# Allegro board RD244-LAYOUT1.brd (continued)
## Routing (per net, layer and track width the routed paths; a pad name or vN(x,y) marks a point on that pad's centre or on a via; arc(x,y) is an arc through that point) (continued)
OUTA1: length 257.6
  CONDUCTIVE3 w0.3: A101.1 106.5,135.28 106.5,110.46 109.99,106.97 117.53,106.97 118.9,105.6 118.9,101.94 122.61,98.23 122.61,93.02 118.23,88.64 118.23,24.02 119.09,23.16 139.66,23.16 142.75,20.07 142.75,10.23 149.22,3.76 189.49,3.76 194.79,9.06 209.76,9.06 210.2,9.5 221,9.5 v1(221.35,9.15)
  BOTTOM w0.3: v1(221.35,9.15) 223.05,7.45 225.4,7.45 226.16,8.21 227.57,8.21
  BOTTOM w0.55: IC303.14 227.57,8.21
OUTA2: length 7.7
  BOTTOM w0.3: R354.1 243.26,6.35 243.59,6.67 244.37,6.67 ; 246.48,6.65 v1(247.25,6.65) ; 238.41,8.21 238.84,8.21 240.7,6.35 241.59,6.35
  BOTTOM w0.45: R354.2 241.59,6.35 ; R356.2 244.37,6.67 ; R355.2 246.48,6.65
  BOTTOM w0.55: 238.41,8.21 IC303.3
OUTB1: length 268.5
  CONDUCTIVE3 w0.3: A101.2 113.04,141.51 112.45,142.1 108.8,142.1 105.2,138.5 105.2,109.9 109.21,105.89 116.81,105.89 118.03,104.67 118.03,101.6 121.65,97.98 121.65,93.25 117.55,89.15 117.55,23.18 118.5,22.23 139.25,22.23 141.4,20.08 141.4,9.72 148.42,2.7 190.46,2.7 195.76,8 217.93,8 218.03,8.1 v1(221.35,8.1)
  BOTTOM w0.3: v1(221.35,8.1) 222.99,6.46 225.69,6.46 226.16,6.93 227.46,6.93
  BOTTOM w0.55: 227.46,6.93 IC303.13
OUTB2: length 12
  BOTTOM w0.3: 238.53,6.93 238.97,6.93 240.75,5.15 241.61,5.15 ; 246.6,5.55 v1(251.6,5.55) ; R357.1 243.13,5.15 243.51,5.53 244.37,5.53
  BOTTOM w0.45: R357.2 241.61,5.15 ; R359.2 244.37,5.53 ; R358.2 246.6,5.55
  BOTTOM w0.55: 238.53,6.93 IC303.4
OUTC1: length 228.8
  CONDUCTIVE4 w0.3: A102.1 110.5,109.06 112.2,107.36 113.43,107.36 118.84,101.95 118.84,96.44 116.7,94.3 116.7,25.61 119.34,22.97 140.58,22.97 145.04,18.51 145.04,12.65 155.4,2.29 201.56,2.29 206.17,6.9 v1(221.35,6.9)
  BOTTOM w0.3: v1(221.35,6.9) 222.59,5.67 227.46,5.67
  BOTTOM w0.55: 227.46,5.67 IC303.12
OUTC2: length 24.7
  TOP w0.3: DP254.1 v1(247.9,2.9)
  BOTTOM w0.3: 258.88,7.97 255.55,7.97 250.47,2.9 v1(247.9,2.9) 246.6,2.9 ; R360.2 240.76,3.95 239.05,5.67 238.54,5.67 ; 244.37,2.88 243.68,2.88 R360.1
  BOTTOM w0.4: 258.88,7.97 IC251.20
  BOTTOM w0.45: R362.2 244.37,2.88 ; R361.2 246.6,2.9
  BOTTOM w0.55: 238.54,5.67 IC303.5
OUTD1: length 243.8
  CONDUCTIVE4 w0.3: A102.2 113.04,125.4 111.94,126.5 109.5,126.5 107.8,124.8 107.8,109.3 111.07,106.03 113.57,106.03 118.18,101.42 118.18,97.03 115.94,94.79 115.94,24.83 118.63,22.14 139.21,22.14 144.11,17.24 144.11,11.49 153.95,1.65 202.37,1.65 206.52,5.8 v1(221.35,5.8)
  BOTTOM w0.3: v1(221.35,5.8) 222.75,4.39 227.46,4.39
  BOTTOM w0.55: 227.46,4.39 IC303.11
OUTD2: length 14.3
  BOTTOM w0.3: v1(251.9,2.85) 256.38,7.33 258.88,7.33 ; 238.34,4.39 239.21,4.39 240.8,2.8 241.57,2.8
  BOTTOM w0.4: 258.88,7.33 IC251.19
  BOTTOM w0.45: R363.2 241.57,2.8
  BOTTOM w0.55: 238.34,4.39 IC303.6
OUTE: length 47.7
  CONDUCTIVE4 w0.5: v1(261.2,7.3) 261.2,11.7 v1(255.5,17.4) 255.5,18.72 256.06,19.28 256.06,45.65 252.6,49.11
  BOTTOM w0.3: 260.23,6.67 260.57,6.67 v1(261.2,7.3)
  BOTTOM w0.4: IC251.18 260.23,6.67
  vias: v1(259.39,117.8) v1(261.36,69.34)
OUTF: length 68.8
  CONDUCTIVE3 w0.5: v1(261.2,6) 262.3,7.1 262.3,13.18 v1(261.05,14.43) 257.25,18.23 257.25,44.56 253.39,48.42
  CONDUCTIVE4 w0.5: v1(259.87,120.42) 259.23,119.78 257.29,119.78 254.43,122.64 244.59,122.64 243.73,123.5 v1(239.42,123.5)
  vias: v1(238.83,77.39) v1(261.35,72.02)
PFC_OFF: length 12.7
  TOP w0.3: 116.32,3.58 114.67,3.58 ; 116.5,4.6 116.5,10.2 DP51.1 118.7,12.4 v1(120.5,12.4)
  TOP w0.4: 114.67,3.58 114.5,3.58
  TOP w0.45: R308.2 116.32,3.58 ; R308.1 116.5,4.6
PN: length 452.1
  TOP w0.3: 219.28,6.22 219.28,5.43
  TOP w0.45: 219.28,6.4 219.28,6.22 ; 219.28,5.43 219.28,5.25
  TOP w0.5: T401.4 223.85,19.5 C414.1
  TOP w0.7: v1(119.59,94.34) v1(119.59,93.54)
  CONDUCTIVE3 w0.3: v1(132.3,4.3) 133.43,5.43 133.43,6.11 134.93,7.61 134.93,14.88 130.11,19.7 116.9,19.7 112.1,24.5 112.1,59.7 113.83,61.43 113.83,93.39 113.54,93.68 A51.4 112.41,97.07 112.41,92.71 113.13,91.99 113.13,62.01 111.34,60.22 111.34,24.08 116.32,19.1 129.72,19.1 134.19,14.63 134.19,7.72 133.64,7.17 v1(133.13,7.17)
  CONDUCTIVE4 w0.5: C54.1 92.24,5.15 96.73,9.64 96.73,15.08 RY1.1
  CONDUCTIVE4 w1: A51.4 113.54,95.39 114.6,94.33 v1(114.6,13.4)
  BOTTOM w0.3: T401.4 222.43,22.5 C407.1 ; 118.17,13.18 118.17,13.92 ; v1(133.13,7.17) 131.36,7.17
  BOTTOM w0.36: 131.36,7.17 131.1,7.17
  BOTTOM w0.45: 118.17,13.92 R60.1 ; R63.1 118.17,13.18
  BOTTOM w0.5: 188.8,31.8 184.3,27.3 178.82,27.3
  BOTTOM w1: A102.4 A101.4
  BOTTOM w1.405: 178.82,27.3 R102.1
  vias: v1(91.8,16.7) v1(108.7,1.9) v1(113.4,13.4) v1(117.6,6.6) v1(118.2,15) v1(123.8,11.3) v1(124.6,11.3) v1(125.83,5.12) v1(126.62,5.12) v1(127.31,15.21) v1(131,14.7) v1(131.1,8.2) v1(199.5,7) v1(199.5,6.2) v1(199.5,3.2) v1(208.5,10.3) v1(209.3,17.43) v1(209.3,16.73) v1(211.3,10.2) v1(212.1,10.2) v1(215.83,2.81) v1(218.32,10.3) v1(218.39,1.64) v1(225.7,9.5) v1(226.79,2.31)
SIG1: length 73.9
  CONDUCTIVE3 w0.5: C2.2 9.48,70.02 FH2.2 FH2.1
  BOTTOM w5: L1.3 44.75,94.25 C1.1 ; 3.17,50.05 3.17,40.33 TB1.2
SIG0013: length 142
  TOP w2: R3.2 R4.1
  CONDUCTIVE3 w0.3: v1(97,3.8) 88.8,12 88.8,26.6 81.9,33.5 C9.1
  CONDUCTIVE3 w0.5: L2.1 53.38,19.88 53.38,14.38 46.44,7.44 25.56,7.44 C7.2
  CONDUCTIVE4 w0.5: L2.4 40.4,27.5 34.47,21.57 34.47,18.97 C8.2
  BOTTOM w2: R3.2 R4.1
  vias: v1(77.9,49.5) v1(77.9,48.7) v1(77.9,47.9) v1(77.9,47.1) v1(77.9,46.3) v1(77.9,45.5) v1(77.9,44.7) v1(78.7,49.5) v1(78.7,48.7) v1(78.7,47.9) v1(78.7,47.1) v1(78.7,46.3) v1(78.7,45.5) v1(78.7,44.7) v1(79.5,49.5) v1(79.5,48.7) v1(79.5,47.9) v1(79.5,47.1) v1(79.5,46.3) v1(79.5,45.5) v1(79.5,44.7) v1(80.3,49.5) v1(80.3,48.7) v1(80.3,47.9) v1(80.3,47.1) v1(80.3,46.3) v1(80.3,45.5) v1(80.3,44.7) v1(81.1,49.5) v1(81.1,48.7) v1(81.1,47.9) v1(81.1,47.1) v1(81.1,46.3) v1(81.1,45.5) v1(81.1,44.7) v1(81.9,49.5) v1(81.9,48.7) v1(81.9,47.9) v1(81.9,47.1) v1(81.9,46.3) v1(81.9,45.5) v1(81.9,44.7)
SIG0032: length 14.4
  BOTTOM w0.3: 124.17,4.72 124.17,3.88 ; 125.2,3.7 128,3.7 128.38,4.08 128.38,4.67 ; 124.17,5.08 124.17,8.72 123.53,9.38 123,9.38 ; 128.28,6.01 128.28,6.93 128.32,6.98 128.32,7.77 ; 128.28,5.07 128.28,5.79
  BOTTOM w0.4: 123,9.38 IC51.13
  BOTTOM w0.45: 124.17,5.08 C63.2 124.17,4.72 ; R65.1 125.2,3.7 ; 124.17,3.88 R65.2 ; 128.38,4.67 R66.2 ; 128.28,4.9 128.28,5.07 ; 128.28,5.79 128.28,6.01
  BOTTOM w0.6: 128.32,7.77 128.32,7.97
SIG0033: length 0.9
  BOTTOM w0.3: 119.86,14.1 119.14,14.1
  BOTTOM w0.45: R59.1 119.86,14.1 ; 119.14,14.1 R60.2
SIG43: length 4.8
  BOTTOM w0.3: R67.2 119.53,5.17 120.1,5.17 ; 120.4,6.03 121.67,6.03 122.47,6.83 122.47,7.77
  BOTTOM w0.45: 120.1,5.17 C65.1 ; C65.2 120.4,6.03
  BOTTOM w0.6: 122.47,7.77 IC51.11
SIG45: length 2.2
  BOTTOM w0.3: C66.2 119.55,8.2 119.72,8.03 120.1,8.03 ; C67.1 119.83,7.17 119.75,7.1 119.39,7.1
  BOTTOM w0.45: 120.1,8.03 C67.2 ; 119.39,7.1 R68.2
SIG47:
  vias: v1(126.8,12.6)
SIG51: length 1.4
  BOTTOM w0.3: 128.32,14.23 128.32,14.75 C58.2
  BOTTOM w0.6: 128.32,14.23 128.32,14.03
SIG52: length 3.6
  BOTTOM w0.3: 121.78,13.28 119.9,13.28 119.62,13 R63.2
  BOTTOM w0.4: 121.78,13.28 IC51.19
SIG0052: length 11.6
  CONDUCTIVE3 w0.5: v1(246.1,129.7) v1(251.9,129.7) v1(257.7,129.7)
SIG53: length 4.6
  BOTTOM w0.3: 126.5,6.95 126.5,9.2 127.33,10.03 127.77,10.03
  BOTTOM w0.4: 127.77,10.03 128.32,10.03
  BOTTOM w0.45: 126.5,6.78 126.5,6.95
SIG0053: length 12
  CONDUCTIVE3 w0.5: v1(276.01,129.7) v1(270.26,129.7) 264.7,129.7 v1(264.2,130.2)
SIG54: length 5.9
  BOTTOM w0.3: 127.63,10.68 126.97,10.68 125.4,9.1 125.4,7
  BOTTOM w0.4: 128.32,10.68 127.63,10.68
  BOTTOM w0.45: 125.4,7 125.4,6.83
SIG0054: length 15
  CONDUCTIVE3 w0.5: v1(264.15,82.5) v1(269.92,82.5) v1(275.68,82.5)
  BOTTOM w0.5: 264.7,76.9 264.7,78.44 ; 266.8,77.14 266.8,78.44
  BOTTOM w0.8: D205.A 266.8,77.14
  BOTTOM w0.83: 266.8,78.44 R206.1 ; 264.7,78.44 R205.1
  BOTTOM w1.1: D204.C 264.7,76.9
SIG0055: length 12.6
  CONDUCTIVE3 w0.5: v1(257.89,82.5) v1(252.11,82.5) 251.22,83.39 v1(245.64,83.39)
SIG56: length 3.3
  BOTTOM w0.3: 129.9,15.05 129.9,13.6 129.57,13.28 128.86,13.28
  BOTTOM w0.4: 128.32,13.28 128.86,13.28
  BOTTOM w0.45: 129.9,15.05 R58.2
SIG116: length 2.2
  BOTTOM w0.5: 246.39,76.4 244.86,76.4
  BOTTOM w0.8: 244.86,76.4 D201.A
  BOTTOM w1.1: 246.75,76.4 246.39,76.4
SIG121: length 13.4
  CONDUCTIVE4 w0.5: v1(260.41,73.25) 264.43,73.25 267.06,70.62 v1(270.4,70.62)
  BOTTOM w0.5: 258.03,73.2 257.01,73.2
  BOTTOM w0.92: C202.2 258.03,73.2 ; 257.01,73.2 C201.2
SIG124: length 11.4
  CONDUCTIVE4 w0.5: v1(258.54,121.21) 259.06,121.73 262.29,121.73 265.09,118.93 v1(268.56,118.93)
SIG136: length 26.8
  TOP w0.5: IC501.5 265,42.86 265.51,43.37 267.93,43.37 269,42.3 269,40.86
  TOP w0.83: 269,40.86 R504.1
  CONDUCTIVE3 w0.5: v1(277.7,40.6) 279.3,42.2 v1(284.8,42.2) 290.5,42.2 ; v1(296.4,42.2) v1(290.6,42.2)
SIG148: length 4.3
  TOP w0.3: v1(266.96,7.44) 268.42,8.9 270.5,8.9
  TOP w0.45: R252.2 270.5,8.9
SIG149: length 3.3
  TOP w0.3: v1(267.8,6.7) 268.9,7.8 270.5,7.8
  TOP w0.45: R253.2 270.5,7.8
SIG150: length 5.8
  TOP w0.3: v1(268.7,6.1) 269.3,6.7 270.62,6.7
  TOP w0.45: R254.2 270.62,6.7
  BOTTOM w0.3: 266.12,6.03 267.18,6.03 267.45,5.75 268.35,5.75 v1(268.7,6.1)
  BOTTOM w0.4: IC251.8 266.12,6.03
SIG151: length 5.6
  TOP w0.3: 270.55,5.6 v1(269.7,5.6)
  TOP w0.45: R255.2 270.55,5.6
  BOTTOM w0.3: 266.12,5.38 266.77,5.38 267.05,5.1 269.2,5.1 v1(269.7,5.6)
  BOTTOM w0.4: IC251.9 266.12,5.38
SIG181: length 4.5
  BOTTOM w0.3: 264.7,2.2 264.1,2.2 263.5,2.8 263.5,3.6 263.98,4.08 264.6,4.08
  BOTTOM w0.4: IC251.11 264.6,4.08
  BOTTOM w0.45: 264.7,2.2 R257.2
SIG199: length 85
  CONDUCTIVE3 w0.5: L2.2 49.25,40.75 37.15,40.75 C4.2
  CONDUCTIVE4 w0.5: C5.2 21.5,46.85 27.15,52.5 L2.3
SIG00792: length 1.1
  TOP w0.3: 106.88,3.02 107.62,3.02
  TOP w0.45: 107.62,3.02 C304.2 ; C305.2 106.88,3.02
SIG00795: length 1.1
  TOP w0.3: 216.58,4.38 217.32,4.38
  TOP w0.45: 217.32,4.38 C307.2 ; C308.2 216.58,4.38
SIG00797: length 4.8
  TOP w0.3: 220.75,1.45 223.32,1.45 223.85,1.98 ; IC302.4 220.72,2.12 220.57,1.98 220.57,1.61
  TOP w0.45: 220.75,1.45 R315.2 220.57,1.61
SIG007110: length 6.6
  TOP w0.3: 110.52,5.08 114.33,5.08 ; 110.35,5.52 110.35,6.27 109.92,6.7 109.92,7.38
  TOP w0.4: 110.52,5.08 110.35,5.08 110.35,5.52 ; 114.33,5.08 114.5,5.08
SIG007129: length 2.1
  TOP w0.3: 217.5,2.58 217.07,2.58 DP305.1
SIG008104: length 1.1
  BOTTOM w0.3: 201.43,8.98 201.43,8.24
  BOTTOM w0.45: 201.43,8.24 R413.2 ; C410.2 201.43,8.98
SIG008110:
  vias: v1(251.64,40.07) v1(251.64,39.37) v1(251.62,31.63) v1(251.62,30.93) v1(252.34,40.07) v1(252.34,39.37) v1(252.32,31.63) v1(252.32,30.93) v1(253.04,40.07) v1(253.04,39.37) v1(253.02,31.63) v1(253.02,30.93) v1(253.74,40.07) v1(253.74,39.37) v1(253.72,31.63) v1(253.72,30.93) v1(254.44,40.07) v1(254.44,39.37) v1(254.42,31.63) v1(254.42,30.93) v1(255.14,40.07) v1(255.14,39.37) v1(255.12,31.63) v1(255.12,30.93)
SIG008111: length 74.9
  BOTTOM w0.3: 205.63,14.9 192.85,14.9 189.55,11.6 C401.2
  BOTTOM w0.65: 205.63,14.9 IC401.7
  BOTTOM w1: F401.2 186.44,11.6 C401.2 187.7,18.15 203.65,34.1 212.42,34.1 213.42,35.1 T401.1
SIG008112: length 11.6
  BOTTOM w1: T401.3 218.7,27.5 Q401.D
SIG008113: length 5.8
  TOP w0.3: v1(206.15,10.15) 206.15,11.02 208.7,13.57
  BOTTOM w0.3: v1(202.85,10.71) 203.24,11.1 203.8,11.1
  BOTTOM w0.45: 203.8,11.1 R409.2
  vias: v1(204.5,12.4)
SIG008116: length 15.1
  BOTTOM w0.3: T401.5 219.31,18.7 218.69,18.08 D402.A ; 223,20.1 223,20.9 ; 212.21,13.63 213.24,13.63 214.18,14.57 214.82,14.57 ; 217.2,13.59 217.2,13.95 216.72,14.43 R411.2 ; 218.69,16.93 218.69,15.97 218.15,15.43 215.18,15.43
  BOTTOM w0.45: R410.2 215.18,15.43 ; 217.2,13.59 C406.2 ; R412.1 223,20.1 ; R410.1 214.82,14.57 ; 223,20.9 C407.2
  BOTTOM w0.65: 212.21,13.63 IC401.2
  BOTTOM w1.2: 218.69,16.93 D402.A
SIG008126: length 9.7
  BOTTOM w0.5: 211.24,2.2 213.79,2.2 215.36,3.77 215.36,5.13 D404.C
  BOTTOM w1: IC402.3 211.24,2.2
  vias: v1(213.2,8.8)
SIG008127: length 6.9
  TOP w0.5: T401.6 218.6,14.9 217.15,13.45 217.15,11.23
  TOP w1.2: 217.15,11.23 D403.A
SIG008129: length 2.4
  BOTTOM w0.3: R407.2 213.46,12.37 212.15,12.37
  BOTTOM w0.65: IC401.3 212.15,12.37
SIG008132:
  vias: v1(213.3,15.38)
SS/EN:
  vias: v1(263.6,8.38)

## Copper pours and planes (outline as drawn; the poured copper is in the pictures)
P50V on TOP: 266.3,36.13 266.3,36.18 266.31,36.23 266.45,36.8 266.45,36.82 266.47,36.92 266.52,37 267.54,38.01 267.54,40.24 266.71,41.07 266.58,41.07 266.45,40.94 266.41,40.91 266.35,40.9 266.1,40.9 265.98,40.93 265.88,41.02 265.85,41.15 265.85,41.8 265.92,41.98 266.1,42.05 266.33,42.05 266.43,42.03 266.51,41.98 268.02,40.44 268.04,40.34 268.04,37.91 268.02,37.81 267.97,37.73 266.97,36.73 267.1,36.18 267.1,36.13 267.1,35.6 266.7,35.2 266.3,35.6
P50V on BOTTOM: 285.05,6.2 284.94,6.24 284.9,6.35 284.9,8.89 284.91,8.95 284.94,9 289.75,13.8 289.75,19.27 289.02,20 281.06,20 281,20.01 280.96,20.04 278.14,22.86 278.11,22.9 278.1,22.96 278.1,38.64 278.11,38.7 278.14,38.74 278.76,39.36 278.8,39.39 278.86,39.4 297.24,39.4 297.3,39.39 297.34,39.36 298.16,38.54 298.19,38.5 298.2,38.44 298.2,22.96 298.19,22.9 298.16,22.86 295.34,20.04 295.3,20.01 295.24,20 290.99,20 290.25,19.26 290.25,13.7 290.23,13.6 290.18,13.52 286.45,9.8 286.45,9.39 286.59,8.82 286.6,8.75 286.6,6.35 286.56,6.24 286.45,6.2
VCC5R0_1 on BOTTOM: 218.93,9.64 218.93,9.73 218.96,9.81 219.19,10.33 219.19,10.97 219.18,10.97 218.95,11.2 219.18,11.43 219.35,11.43 219.4,11.42 219.73,11.35 220.09,11.35 220.14,11.34 220.19,11.31 221.2,10.3 223.24,10.3 223.77,10.83 223.82,10.86 223.88,10.88 225.95,10.88 226.27,10.94 226.32,10.95 226.51,10.95 226.55,10.99 226.6,11.02 226.66,11.03 227.1,11.03 227.63,11.26 227.71,11.29 227.79,11.29 228.28,11.29 228.69,10.88 228.28,10.47 227.46,10.47 227.41,10.48 227.37,10.5 226.32,10.5 226.27,10.51 225.95,10.57 223.94,10.57 223.41,10.04 223.36,10.01 223.3,10 221.14,10 221.08,10.01 221.03,10.04 220.03,11.05 219.73,11.05 219.49,10.81 219.49,10.33 219.72,9.81 219.74,9.73 219.75,9.64 219.75,9.28 219.34,8.86 218.93,9.28
VCC5R0_2 on BOTTOM: 237.72,10.47 237.31,10.88 237.72,11.29 238.45,11.29 238.54,11.29 238.62,11.26 239.14,11.03 240.52,11.03 242.09,12.61 242.14,12.64 242.2,12.65 243.17,12.65 243.49,12.72 243.54,12.72 243.72,12.72 243.94,12.5 243.72,12.28 243.54,12.28 243.49,12.28 243.17,12.35 242.26,12.35 240.43,10.51 240.38,10.48 240.32,10.47
VCC12R0_2 on TOP (solid shape): 284.12,14.63 284.72,14.83 285.66,14.47 285.98,14 285.66,13.53 284.72,13.17 284.63,13.15 284.54,13.14 284.08,13.45 284.2,14
VCC12R0_2 on BOTTOM (solid shape): 284.12,14.63 284.72,14.83 285.66,14.47 285.98,14 285.66,13.53 284.72,13.17 284.63,13.15 284.54,13.14 284.08,13.45 284.2,14
VCC12R0_2 on CONDUCTIVE5 (solid shape): 284.12,14.63 284.72,14.83 285.66,14.47 285.98,14 285.66,13.53 284.72,13.17 284.63,13.15 284.54,13.14 284.08,13.45 284.2,14
VCC12R0_2 on TOP: 250.38,43.36 250.27,43.4 250.23,43.51 250.23,46.64 250.27,46.75 250.38,46.79 253.56,46.79 253.67,46.75 253.71,46.64 253.71,43.51 253.67,43.4 253.56,43.36
VCC12R0_2 on BOTTOM: 283.9,15.49 283.9,16.43 282.9,17.43 261.42,17.43 261.23,17.47 261.07,17.58 256.9,21.75 256.79,21.91 256.75,22.1 256.75,33.49 256.79,33.68 256.9,33.84 257.75,34.7 257.75,42.02 256.35,43.42 251,43.42 250.5,43.92 251,44.42 256.56,44.42 256.75,44.38 256.91,44.27 258.6,42.58 258.71,42.42 258.75,42.23 258.75,34.49 258.71,34.3 258.6,34.14 257.75,33.28 257.75,22.31 261.63,18.43 283.11,18.43 283.3,18.39 283.46,18.28 284.75,17 284.86,16.83 284.9,16.64 284.9,15.49 285.26,14.24 285.03,13.68 284.42,13.75 284.4,13.77 284.38,13.75 283.77,13.68 283.54,14.24
VCC12R0_2 on BOTTOM: 235.98,120.75 235.66,120.72 235.57,121.03 235.59,121.07 236.07,121.56 236.15,121.61 236.25,121.63 249.4,121.63 249.89,122.13 249.95,122.17 250.01,122.19 250.04,122.2 250.07,122.2 251.57,122.2 251.62,122.24 251.68,122.25 251.95,122.25 252.06,122.21 252.1,122.1 252.1,121.78 252.06,121.67 251.95,121.63 251.68,121.63 251.62,121.64 251.58,121.67 251.55,121.7 250.17,121.7 249.68,121.2 249.65,121.18 249.61,121.16 249.56,121.14 249.5,121.13 236.35,121.13
VCC12R0_2 on BOTTOM: 253.5,74.76 253.45,74.77 253.41,74.79 237.6,74.79 237.5,74.81 237.42,74.86 236.64,75.65 236.14,75.65 236.08,75.59 236.04,75.56 235.98,75.55 235.66,75.55 235.6,75.56 235.56,75.59 235.5,75.65 235.47,75.69 235.46,75.75 235.46,76.07 235.47,76.13 235.5,76.17 235.52,76.19 235.56,76.22 235.62,76.23 235.96,76.23 236.02,76.22 236.06,76.19 236.1,76.15 236.74,76.15 236.84,76.13 236.92,76.08 237.7,75.29 253.38,75.29 253.4,75.31 253.44,75.34 253.5,75.35 254.1,75.35 254.21,75.31 254.25,75.2 254.25,74.91 254.21,74.8 254.1,74.76
VCC12R0_2 on CONDUCTIVE3: 251.05,43.52 251.01,43.53 250.98,43.55 250.6,43.93 250.58,43.96 250.57,44 250.57,44.17 250.6,44.24 250.67,44.27 253.43,44.27 253.5,44.24 253.53,44.17 253.53,43.62 253.5,43.55 253.43,43.52
VCC12R0_2 on CONDUCTIVE3: 235.62,58.22 235.57,58.3 235.55,58.4 235.55,101.96 235.48,102.45 235.48,102.55 235.55,103.04 235.55,120.39 235.48,120.88 235.48,120.92 235.55,121.1 235.73,121.17 235.76,121.18 235.8,121.18 235.84,121.18 235.87,121.17 236.05,121.1 236.12,120.92 236.12,120.88 236.05,120.39 236.05,103.04 236.12,102.55 236.12,102.45 236.05,101.96 236.05,58.5 242.01,52.54 242.08,52.37 242.01,52.19 241.83,52.12 241.66,52.19
VCC18R0_1 on TOP: 197.01,2.03 196.95,2.04 196.91,2.08 196.55,2.44 196.51,2.49 196.5,2.54 196.5,4.15 196.27,4.28 196.2,4.45 196.34,4.56 196.36,4.56 196.36,4.58 196.47,4.73 196.64,4.65 196.83,4.3 197.4,3.73 198.04,3.12 198.07,3.08 198.08,3.02 198.08,2.36 198.07,2.3 198.04,2.26 197.86,2.08 197.81,2.04 197.75,2.03
VCC18R0_1 on BOTTOM: 111.75,7.15 111.26,7.64 111.24,7.65 111.22,7.67 110.69,8.19 110.66,8.24 110.65,8.3 110.65,8.74 108.42,10.97 108.39,11.02 108.38,11.07 108.38,14.84 108.26,15.22 108.25,15.26 108.25,15.3 108.25,15.5 108.53,15.78 108.8,15.5 108.8,15.3 108.8,15.26 108.79,15.22 108.67,14.84 108.67,11.14 110.94,8.86 110.95,8.8 110.95,8.36 111.28,8.03 112.15,8.03 112.26,7.99 112.3,7.88 112.3,7.46 112.29,7.4 112.26,7.36 112.25,6.6 112,6.35 111.75,6.6
VCC18R0_1 on CONDUCTIVE4: outline of 129 points within 105.62,6.37 116.59,139.08
$BN000001 on TOP: 221.34,3.43 221.28,3.44 221.23,3.47 220.9,3.8 220.73,3.8 220.62,3.84 220.58,3.95 220.58,4.05 220.62,4.16 220.73,4.2 221.16,4.2 222.4,5.44 222.4,5.86 222.44,5.97 222.55,6.01 222.85,6.01 222.96,5.97 223,5.86 223,5.05 223.21,4.84 223.24,4.8 223.25,4.74 223.25,3.91 223.24,3.85 223.21,3.81 222.87,3.47 222.82,3.44 222.76,3.43
$BN000001 on TOP: 169.74,100.22 169.68,100.23 169.64,100.26 168.04,101.86 168,101.91 167.99,101.97 167.99,107.71 164.21,111.5 130.5,111.5 129.5,112.5 130.5,113.5 164.62,113.5 165,113.42 165.33,113.21 173.02,105.51 178.65,105.51 178.71,105.5 178.75,105.47 179.97,104.25 180,104.21 180.01,104.15 180.01,100.8 180,100.74 179.97,100.7 179.53,100.26 179.49,100.23 179.43,100.22
$BN000001 on BOTTOM: 71.71,105.1 71.65,105.11 71.61,105.14 71.09,105.66 71.06,105.7 71.05,105.76 71.05,108.24 71.06,108.3 71.09,108.34 71.61,108.86 71.65,108.89 71.71,108.9 74.29,108.9 74.35,108.89 74.39,108.86 74.91,108.34 74.94,108.3 74.95,108.24 74.95,105.56 74.94,105.5 74.91,105.46 74.59,105.14 74.55,105.11 74.49,105.1
$BN000001 on BOTTOM: outline of 130 points within 119.5,3.8 218.77,105.11
$BN000001 on BOTTOM: 130.82,11.75 130.77,11.76 130.45,11.82 129.36,11.82 129.06,11.78 129.02,11.78 128.32,11.78 128.12,11.97 128.32,12.18 129.02,12.18 129.06,12.17 129.36,12.12 130.45,12.12 130.77,12.19 130.82,12.2 131.18,12.2 131.23,12.19 131.55,12.13 131.87,12.19 131.92,12.2 132.19,12.2 132.24,12.19 132.57,12.12 133.16,12.12 134.49,13.46 134.54,13.49 134.6,13.5 135.07,13.5 135.75,13.8 135.84,13.81 136.96,13.81 137.06,13.8 137.15,13.77 137.73,13.5 138.21,13.5 138.42,13.56 138.47,13.57 138.51,13.56 138.57,13.53 138.61,13.47 138.61,13.45 138.65,13.36 138.62,13.27 138.6,13.24 138.58,13.08 138.42,13.04 138.04,13.15 137.62,13.15 137.15,12.93 137.06,12.9 136.96,12.89 135.84,12.89 135.75,12.9 135.07,13.2 134.66,13.2 133.33,11.87 133.28,11.84 133.22,11.82 132.57,11.82 132.24,11.76 132.19,11.75 131.92,11.75 131.87,11.76 131.55,11.82 131.23,11.76 131.18,11.75
$BN000002 on BOTTOM: 106.6,3.46 106.56,3.48 106.36,3.65 106.29,3.9 106.29,4.56 106.3,4.65 106.33,4.75 106.5,5.11 106.5,5.67 106.2,6.35 106.19,6.44 106.19,7.1 106.65,7.56 107.11,7.1 107.11,6.44 107.1,6.35 107.07,6.25 106.9,5.89 106.9,5.33 107.2,4.65 107.21,4.56 107.21,3.9 107.04,3.54 106.65,3.45
$BN000002 on BOTTOM: 136.5,10.09 136.04,10.55 136.5,11.01 136.96,11.01 137.06,11 137.15,10.97 137.62,10.75 138.04,10.75 138.42,10.86 138.47,10.87 138.51,10.86 138.59,10.81 138.61,10.72 138.61,10.7 138.62,10.68 138.65,10.59 138.61,10.5 138.61,10.48 138.55,10.36 138.42,10.34 138.21,10.4 137.73,10.4 137.15,10.13 137.06,10.1 136.96,10.09
$BN000002 on BOTTOM: 101.59,4.02 101.61,4.16 101.66,4.3 102.04,5.02 102.04,6.08 101.66,6.8 101.61,6.94 101.59,7.08 101.59,7.4 101.88,7.91 102.47,7.93 103.19,7.55 103.71,7.55 103.76,7.56 103.81,7.56 103.95,7.56 104,7.56 104.08,7.54 104.12,7.53 104.4,7.01 103.95,6.64 103.81,6.64 103.71,6.65 103.04,6.95 102.78,6.95 102.76,6.87 102.72,6.8 102.34,6.08 102.34,5.02 102.72,4.3 102.78,4.16 102.79,4.02 102.79,3.7 102.19,3.1 101.59,3.7
ACIN on TOP: 103.97,3.2 103.98,3.25 104.05,3.58 104.05,3.81 104,3.86 103.82,3.9 103.65,3.9 103.59,3.91 103.54,3.94 103.21,4.28 103,4.28 102.61,4.16 102.57,4.15 102.53,4.15 102.5,4.15 102.22,4.42 102.5,4.7 102.53,4.7 102.57,4.7 102.61,4.69 103,4.58 103.28,4.58 103.33,4.56 103.71,4.2 103.82,4.2 104.15,4.27 104.19,4.28 104.22,4.43 104.22,4.55 104.24,4.61 105.07,5.46 105.07,5.66 104.75,6.22 104.74,6.26 104.73,6.3 104.84,6.44 105.01,6.38 105.22,6.01 105.58,6.01 105.79,6.38 105.96,6.44 106.07,6.3 106.06,6.26 106.05,6.22 105.66,5.55 105.66,5.42 105.85,5.22 107.05,5.22 107.37,5.29 107.42,5.3 107.6,5.3 107.83,5.08 107.6,4.85 107.42,4.85 107.37,4.86 107.05,4.92 104.96,4.92 104.53,4.49 104.53,4.43 104.59,4.1 104.6,4.05 104.6,3.96 104.59,3.9 104.56,3.86 104.35,3.65 104.35,3.58 104.42,3.25 104.42,3.2 104.42,3.02 104.2,2.8 103.97,3.02
ACIN on BOTTOM: 91.31,7.44 91.32,7.58 91.38,7.72 91.65,8.25 91.4,8.82 91.39,8.92 91.39,10.16 91.4,10.25 91.43,10.35 91.7,10.93 91.7,11.12 91.45,11.69 91.44,11.78 91.44,12.05 91.9,12.51 92.36,12.05 92.36,11.78 92.35,11.69 92.32,11.59 92.05,11.01 92.05,10.82 92.3,10.25 92.31,10.16 92.31,8.92 92.3,8.82 92.27,8.72 92.1,8.36 92.49,7.58 92.51,7.44 92.51,7.3 91.91,6.7 91.31,7.3
CONN002 on BOTTOM: 142.66,121.08 142.55,121.12 142.51,121.23 142.51,126.61 142.55,126.72 142.66,126.76 154.35,126.76 154.46,126.72 154.5,126.61 154.5,121.23 154.46,121.12 154.35,121.08
CONN002 on CONDUCTIVE3, CONDUCTIVE4: 184.33,66.1 184.29,66.11 184.26,66.13 182.03,68.36 182.01,68.39 182,68.43 182,104.8 179.68,107.12 149.02,107.12 148.98,107.13 148.95,107.15 142.23,113.87 142.21,113.9 142.2,113.94 142.2,125.56 142.21,125.6 142.23,125.63 143.27,126.67 143.3,126.69 143.34,126.7 153.46,126.7 153.5,126.69 153.53,126.67 154.47,125.73 154.49,125.7 154.5,125.66 154.5,123.2 157.12,120.58 183.08,120.58 183.12,120.57 183.15,120.55 183.78,119.92 195.67,119.92 195.71,119.91 195.74,119.89 197.11,118.52 197.13,118.49 197.14,118.45 197.14,113.21 197.13,113.17 197.11,113.14 195.77,111.8 195.74,111.78 195.7,111.78 192.66,111.78 190.88,110 190.88,104.93 190.88,104.89 190.86,104.86 189.85,103.85 189.85,75.85 191.84,73.86 196.26,73.86 196.3,73.85 196.33,73.83 197.27,72.89 197.29,72.86 197.3,72.82 197.3,67.59 197.29,67.55 197.27,67.52 195.88,66.13 195.85,66.11 195.81,66.1
CONN003 on TOP: 187.91,85.35 187.85,85.36 187.81,85.39 184.04,89.16 184.01,89.2 184,89.26 184,103.1 183.39,105.76 181.67,107.87 181.62,107.92 181.61,107.99 181.61,112.55 181.6,112.58 181.6,112.6 181.6,133.76 181.61,133.82 181.64,133.86 186.56,138.78 186.6,138.81 186.66,138.82 191.62,138.82 193.61,140.81 193.61,146.84 193.62,146.9 193.65,146.94 193.96,147.25 194,147.28 194.06,147.29 196.3,147.29 196.36,147.28 196.4,147.25 197.06,146.59 197.09,146.55 197.1,146.49 197.1,132.64 197.09,132.58 197.06,132.54 195.91,131.39 195.87,131.36 195.81,131.35 190.86,131.35 189.81,130.3 189.81,101.1 192,98.91 195.05,98.91 195.11,98.9 195.15,98.87 197.06,96.96 197.09,96.92 197.1,96.86 197.1,86.58 197.09,86.52 197.06,86.48 195.97,85.39 195.93,85.36 195.87,85.35
CONN003 on TOP: 170.9,128.86 170.84,128.87 170.8,128.9 170.1,129.6 146.06,129.6 146,129.61 145.96,129.64 142.54,133.06 142.51,133.1 142.5,133.16 142.5,143.45 142.54,143.56 142.65,143.6 154.35,143.6 154.46,143.56 154.5,143.45 154.5,138.8 156.75,136.55 171.93,136.55 171.99,136.54 172.03,136.51 174.26,134.28 174.29,134.24 174.3,134.18 174.3,130.21 174.29,130.15 174.26,130.11 173.05,128.9 173.01,128.87 172.95,128.86
CONN003 on BOTTOM: 142.66,138.08 142.55,138.12 142.51,138.23 142.51,143.61 142.55,143.72 142.66,143.76 154.35,143.76 154.46,143.72 154.5,143.61 154.5,138.23 154.46,138.12 154.35,138.08
CONN003 on BOTTOM: 193.43,96.62 193.37,96.63 193.33,96.66 192.86,97.13 192.83,97.17 192.82,97.23 192.82,98.51 192.83,98.57 192.86,98.61 193.14,98.89 193.18,98.92 193.24,98.93 194.59,98.93 194.65,98.92 194.69,98.89 194.87,98.71 194.9,98.67 194.91,98.61 194.91,97.08 194.9,97.02 194.87,96.98 194.55,96.66 194.51,96.63 194.45,96.62
CONN003 on BOTTOM: 194.21,144.72 194.15,144.73 194.11,144.76 193.56,145.31 193.53,145.35 193.52,145.41 193.52,146.86 193.53,146.92 193.56,146.96 193.92,147.32 193.96,147.35 194.02,147.36 195.19,147.36 195.25,147.35 195.29,147.32 195.65,146.96 195.68,146.92 195.69,146.86 195.69,145.18 195.68,145.12 195.65,145.08 195.33,144.76 195.29,144.73 195.23,144.72
CONN003 on CONDUCTIVE2: 146.06,129.6 146,129.61 145.96,129.64 142.54,133.06 142.51,133.1 142.5,133.16 142.5,143.45 142.54,143.56 142.65,143.6 154.35,143.6 154.46,143.56 154.5,143.45 154.5,138.8 156.75,136.55 172.35,136.55 172.39,136.54 172.42,136.52 174.27,134.67 174.29,134.64 174.3,134.6 174.3,130.5 174.29,130.46 174.27,130.43 173.47,129.63 173.44,129.61 173.4,129.6
CONN003 on CONDUCTIVE2: 187.96,85.3 187.9,85.31 187.86,85.34 184.04,89.16 184.01,89.2 184,89.26 184,103.1 183.39,105.76 181.67,107.87 181.62,107.92 181.61,107.99 181.61,112.55 181.6,112.58 181.6,112.6 181.6,133.76 181.61,133.82 181.64,133.86 186.56,138.78 186.6,138.81 186.66,138.82 191.62,138.82 193.42,140.62 193.42,146.65 193.43,146.71 193.46,146.75 193.96,147.25 194,147.28 194.06,147.29 196.3,147.29 196.36,147.28 196.4,147.25 197.06,146.59 197.09,146.55 197.1,146.49 197.1,132.64 197.09,132.58 197.06,132.54 195.84,131.32 195.8,131.29 195.74,131.28 190.84,131.28 189.81,130.25 189.81,102.1 192.89,99.02 194.94,99.02 195,99.01 195.04,98.98 197.06,96.96 197.09,96.92 197.1,96.86 197.1,86.58 197.09,86.52 197.06,86.48 195.92,85.34 195.88,85.31 195.82,85.3
CONN004 on TOP: 249.66,51.1 249.6,51.11 249.56,51.14 244.15,56.55 244.12,56.59 244.11,56.65 244.11,71.67 244.12,71.73 244.15,71.77 246,73.62 246.04,73.65 246.1,73.66 254.88,73.66 254.94,73.65 254.98,73.62 260.56,68.04 268.7,68.04 268.76,68.03 268.8,68 270.96,65.84 270.99,65.8 271,65.74 271,59.26 270.99,59.2 270.96,59.16 266.04,54.24 266,54.21 265.94,54.2 254.1,54.2 251.04,51.14 251,51.11 250.94,51.1
CONN004 on TOP: outline of 88 points within 279.99,40.55 298.9,132.04 ; 4 cut-outs
CONN004 on TOP: 263.63,40.99 263.57,40.99 262.78,41.25 262.44,41.25 261.85,41.01 261.77,41 261.3,41 260.9,41.4 261.3,41.8 261.77,41.8 261.85,41.79 261.92,41.77 262.44,41.55 262.87,41.55 263.5,42.18 263.5,42.35 263.5,42.4 263.51,42.45 263.66,43.04 263.66,44.41 263.68,44.51 264.43,45.28 264.51,45.33 264.6,45.35 265.6,45.35 265.85,45.1 265.6,44.85 264.71,44.85 264.16,44.31 264.16,43.04 264.32,42.4 264.32,42.35 264.32,41.4 264.2,41.11 263.91,40.99
CONN004 on TOP: outline of 92 points within 260.07,85.65 276.01,102.95
CONN004 on TOP: 265.88,37.57 265.82,37.58 265.78,37.61 265.72,37.67 265.69,37.71 265.68,37.77 265.68,39.97 265.72,40.08 265.83,40.12 266.35,40.12 266.46,40.08 266.5,39.97 266.5,37.89 266.49,37.83 266.46,37.79 266.28,37.61 266.24,37.58 266.18,37.57
CONN004 on TOP: 244.35,99.5 244.24,99.54 244.2,99.65 244.2,118.03 244.21,118.09 244.24,118.13 245.87,119.76 245.91,119.79 245.97,119.8 252.69,119.8 252.75,119.79 252.79,119.76 254.35,118.2 255.52,118.2 255.58,118.19 255.62,118.16 257.27,116.51 270.21,116.51 270.27,116.5 270.31,116.47 270.76,116.02 270.79,115.98 270.8,115.92 270.8,108.66 270.79,108.6 270.76,108.56 266.66,104.46 266.62,104.43 266.56,104.42 253.17,104.42 248.29,99.54 248.25,99.51 248.19,99.5
CONN004 on BOTTOM: 274.98,4.78 274.89,4.75 274.8,4.79 274.78,4.79 274.66,4.85 274.64,4.98 274.7,5.19 274.7,5.44 274.4,6.11 274.39,6.21 274.39,7.21 274.4,7.31 274.43,7.4 274.7,7.98 274.7,9.01 274.14,9.57 273.85,9.57 273.53,9.51 273.48,9.5 273.22,9.5 273.17,9.51 272.85,9.57 272.61,9.57 272.51,9.56 272.46,9.55 272.12,9.55 272.07,9.56 271.98,9.57 271.65,9.57 271.33,9.51 271.28,9.5 270.92,9.5 270.87,9.51 270.55,9.57 270.23,9.51 270.18,9.5 270,9.5 269.77,9.72 270,9.95 270.18,9.95 270.23,9.94 270.55,9.88 270.87,9.94 270.92,9.95 271.28,9.95 271.33,9.94 271.42,9.93 271.75,9.93 272.07,9.99 272.12,10 272.46,10 272.51,9.99 272.84,9.93 273.08,9.93 273.17,9.94 273.22,9.95 273.48,9.95 273.53,9.94 273.85,9.88 274.2,9.88 274.26,9.86 274.96,9.18 274.99,9.13 275,9.07 275,7.98 275.27,7.4 275.3,7.31 275.31,7.21 275.31,6.21 275.3,6.11 275.27,6.02 275.05,5.55 275.05,5.36 275.16,4.98 275.17,4.93 275.16,4.89 275.11,4.81 275.02,4.79 275,4.79
CONN004 on BOTTOM: 291.16,135.3 291.1,135.31 291.06,135.34 290.1,136.3 282.75,136.3 282.64,136.34 282.6,136.45 282.6,138.84 282.61,138.9 282.64,138.94 283.13,139.43 283.18,139.46 283.24,139.47 288.96,139.47 289.02,139.46 289.07,139.43 289.26,139.24 289.29,139.2 289.3,139.14 289.3,138.8 291.9,136.2 295.55,136.2 295.66,136.16 295.7,136.05 295.7,135.45 295.66,135.34 295.55,135.3
CONN004 on BOTTOM: 274.69,143.5 274.58,143.54 274.54,143.65 274.54,148.28 274.58,148.39 274.69,148.43 281.48,148.43 281.59,148.39 281.63,148.28 281.63,144.83 281.6,144.71 281.5,144.61 281.38,144.58 277.6,144.58 276.56,143.54 276.52,143.51 276.46,143.5
CONN004 on BOTTOM: 246.82,102.49 246.76,102.5 246.72,102.53 244.15,105.1 244.12,105.14 244.11,105.2 244.11,117.98 244.12,118.04 244.15,118.08 244.81,118.74 244.85,118.77 244.91,118.78 251.96,118.78 252.02,118.77 252.06,118.74 255.9,114.9 269.94,114.9 270,114.89 270.04,114.86 270.76,114.14 270.79,114.1 270.8,114.04 270.8,108.66 270.79,108.6 270.76,108.56 266.56,104.36 266.52,104.33 266.46,104.32 253.03,104.32 251.24,102.53 251.2,102.5 251.14,102.49
CONN004 on BOTTOM: 274.91,101.6 274.85,101.61 274.81,101.64 274.51,101.94 274.48,101.98 274.47,102.04 274.47,105.12 274.48,105.18 274.51,105.22 274.67,105.38 274.71,105.41 274.77,105.42 278.25,105.42 278.36,105.38 278.4,105.27 278.4,101.75 278.36,101.64 278.25,101.6
CONN004 on BOTTOM: 246.15,143.7 246.04,143.74 246,143.85 246,147.21 246.04,147.32 246.15,147.36 247.85,147.36 247.96,147.32 248,147.21 248,143.85 247.96,143.74 247.85,143.7
CONN004 on BOTTOM: 269.95,7.99 269.96,8.04 270.01,8.3 269.66,8.65 269.41,8.65 269.28,8.52 269.23,8.49 269.18,8.47 268.98,8.47 268.65,8.41 268.6,8.4 268.42,8.4 268.37,8.41 268.05,8.47 266.46,8.47 266.16,8.43 266.12,8.43 265.36,8.43 265.16,8.62 265.36,8.82 266.12,8.82 266.16,8.82 266.46,8.78 268.05,8.78 268.37,8.84 268.42,8.85 268.6,8.85 268.65,8.84 268.98,8.78 269.11,8.78 269.32,8.98 269.37,9.01 269.43,9.03 269.45,9.03 269.77,9.09 269.82,9.1 270,9.1 270.17,9.02 270.22,8.83 270.19,8.68 270.19,8.66 270.19,8.55 270.31,8.42 270.39,8.04 270.4,7.99 270.4,7.85 270.18,7.62 269.95,7.85
CONN004 on BOTTOM: 276.34,10.99 276.25,11 275.57,11.3 274.85,11.3 274.79,11.31 274.74,11.34 274.71,11.38 273.95,11.38 273.63,11.31 273.58,11.3 273.24,11.3 273.19,11.31 272.86,11.38 272.61,11.38 272.51,11.36 272.46,11.35 272.3,11.35 272.07,11.57 272.3,11.8 272.46,11.8 272.51,11.79 272.84,11.72 273.09,11.72 273.19,11.74 273.24,11.75 273.58,11.75 273.63,11.74 273.95,11.68 274.77,11.68 274.83,11.66 274.91,11.6 275.57,11.6 276.25,11.9 276.34,11.91 277,11.91 277.46,11.45 277,10.99
CONN004 on BOTTOM: outline of 116 points within 274.25,35.55 298.9,131.22 ; 10 cut-outs
CONN004 on CONDUCTIVE3: 275.24,45.15 275.27,45.22 275.34,45.25 276.16,45.25 276.5,45.59 276.5,46.74 276.53,46.81 276.6,46.84 277.25,46.84 277.25,49.46 276.6,49.46 276.53,49.49 276.5,49.56 276.5,69.24 276.51,69.3 276.54,69.34 282.32,75.12 282.35,75.14 282.39,75.15 285.2,75.15 285.2,81.05 282.91,81.05 282.84,81.08 282.81,81.15 282.81,123.35 282.84,123.42 282.91,123.45 285.1,123.45 285.2,123.45 285.3,123.45 285.3,129.35 285.07,129.35 282.91,129.35 282.84,129.38 282.81,129.45 282.81,140.2 282.84,140.27 282.91,140.3 283.7,140.3 283.7,143.1 282.91,143.1 282.84,143.13 282.81,143.2 282.81,143.57 282.82,143.61 282.84,143.64 282.97,143.77 283,143.79 283.04,143.8 286.74,143.8 286.8,143.79 286.84,143.76 298.85,131.75 298.88,131.71 298.89,131.65 298.89,43.12 298.85,43.01 298.74,42.97 276.65,42.97 276.54,43.01 276.5,43.12 276.5,44.61 276.16,44.95 275.34,44.95 275.27,44.98 275.24,45.05 ; 14 cut-outs
CONN004 on CONDUCTIVE3: 252.7,136.35 252.6,136.37 252.52,136.42 246.82,142.12 246.77,142.2 246.75,142.3 246.75,145.8 246.72,145.83 246.67,145.91 246.65,146 246.65,147 246.67,147.09 246.72,147.17 246.74,147.19 246.82,147.24 246.91,147.26 247.06,147.26 247.15,147.24 247.23,147.19 247.3,147.12 247.35,147.04 247.37,146.95 247.37,146.02 247.35,145.93 247.3,145.85 247.25,145.8 247.25,142.4 252.8,136.85 272.1,136.85 275.75,140.5 275.75,146.62 275.72,146.65 275.67,146.73 275.65,146.82 275.65,147.81 275.72,147.99 275.9,148.06 276.09,148.06 276.18,148.04 276.26,147.99 276.31,147.94 276.36,147.86 276.38,147.77 276.38,146.85 276.36,146.76 276.31,146.68 276.25,146.62 276.25,140.4 276.23,140.3 276.18,140.22 272.38,136.42 272.3,136.37 272.2,136.35
CONN004 on CONDUCTIVE4: 288.18,138.8 288.25,139.29 288.25,143.15 286.37,145.03 277.41,145.03 277.31,145.05 277.23,145.1 275.73,146.6 275.68,146.68 275.66,146.78 275.66,147.8 275.73,147.98 275.91,148.05 276.09,148.05 276.26,147.98 276.34,147.8 276.34,146.71 277.51,145.53 286.47,145.53 286.57,145.51 286.65,145.46 288.68,143.43 288.73,143.35 288.75,143.25 288.75,139.29 288.82,138.8 288.82,138.76 288.72,138.56 288.5,138.52 288.28,138.56 288.18,138.76
CS on TOP: 244.79,43.35 244.68,43.39 244.64,43.5 244.64,46.35 244.68,46.46 244.79,46.5 246.79,46.5 246.9,46.46 246.94,46.35 246.94,43.5 246.9,43.39 246.79,43.35
CS on TOP: 259.71,7.55 259.6,7.59 259.56,7.7 259.56,7.84 259.3,8.1 259.16,8.1 258.59,7.85 258.49,7.84 253.5,7.84 253.04,8.3 253.5,8.76 258.49,8.76 258.59,8.75 259.26,8.45 259.72,8.45 259.77,8.44 259.82,8.41 259.93,8.3 259.96,8.26 259.97,8.2 259.97,8.03 260.03,7.97 260.06,7.93 260.07,7.87 260.07,7.7 260.03,7.59 259.92,7.55
CS on TOP: 257.67,1.43 257.55,1.46 257.49,1.58 257.5,1.61 257.51,1.65 257.5,1.69 257.49,1.72 257.55,1.84 257.67,1.87 258,1.8 258.19,1.8 258.55,2.16 258.55,3.05 258.48,3.37 258.48,3.48 258.54,3.63 258.7,3.7 258.99,3.7 259.04,3.69 259.07,3.67 259.95,3.67 260.27,3.74 260.32,3.75 260.5,3.75 260.73,3.52 260.5,3.3 260.32,3.3 260.27,3.31 259.95,3.38 259.15,3.38 258.85,3.08 258.85,2.1 258.84,2.04 258.36,1.54 258.31,1.51 258.25,1.5 258,1.5
CS on BOTTOM: 265.36,10.38 265.07,10.61 265.23,10.94 265.61,11.14 265.85,11.37 265.85,11.45 265.75,11.55 265.5,11.55 265.45,11.51 265.39,11.5 265.15,11.5 265.04,11.54 265,11.65 265,11.95 265.04,12.06 265.15,12.1 265.39,12.1 265.45,12.09 265.49,12.06 265.55,12 266.4,12 266.51,11.96 266.55,11.85 266.55,11.71 266.54,11.65 266.51,11.61 266.15,11.25 266.15,11.01 266.3,10.86 266.33,10.85 266.44,10.85 266.82,10.96 266.92,10.96 266.99,10.9 267.01,10.86 267.01,10.82 267.01,10.78 267.03,10.75 267.04,10.72 267.05,10.65 267.01,10.58 266.95,10.46 266.82,10.44 266.52,10.53 266.4,10.53 265.94,10.38 265.9,10.38
CS on BOTTOM: 257.45,1.89 257.46,1.94 257.5,2.15 257.5,2.25 257.43,2.57 257.43,2.59 257.33,2.61 257.21,2.49 257.17,2.47 257.13,2.45 256.79,2.38 256.74,2.38 256.62,2.38 256.4,2.6 256.62,2.83 256.74,2.83 256.79,2.82 257.05,2.76 257.17,2.88 257.22,2.91 257.27,2.92 257.6,2.99 257.71,2.99 258.04,2.92 258.11,2.92 258.62,3.43 258.64,3.45 258.67,3.47 259.04,3.61 259.09,3.62 259.14,3.62 259.64,3.62 259.94,3.33 259.64,3.02 259.14,3.02 259.09,3.03 259.04,3.04 258.76,3.15 258.28,2.67 258.23,2.64 258.18,2.62 258.04,2.62 257.82,2.36 257.82,2.27 257.89,1.94 257.9,1.89 257.9,1.75 257.68,1.52 257.45,1.75
CS on BOTTOM: 268.3,2.98 268.25,2.98 267.92,3.05 267.87,3.05 267.66,3.01 267.62,3 267.14,3 267.08,3.01 267.03,3.04 266.9,3.17 266.36,3.17 265.95,3.04 265.9,3.03 265.86,3.02 265.36,3.02 265.06,3.33 265.36,3.62 265.86,3.62 265.9,3.62 265.95,3.61 266.36,3.48 267.57,3.48 267.62,3.47 267.66,3.44 267.99,3.38 268.04,3.38 268.25,3.42 268.3,3.42 268.48,3.42 268.7,3.2 268.48,2.98
CS on CONDUCTIVE3: 259.41,2.08 259.37,2.3 259.41,2.52 259.61,2.62 259.65,2.62 260.14,2.55 262.8,2.55 265.45,5.2 265.45,9.5 265.47,9.6 265.52,9.68 266.34,10.5 266.64,10.89 266.66,10.92 266.78,10.99 266.92,10.98 266.94,10.98 267.01,10.93 267.06,10.86 267.14,10.8 267.18,10.72 267.19,10.58 267.12,10.46 267.09,10.44 266.7,10.14 265.95,9.4 265.95,5.1 266.5,4.55 271.06,4.55 271.55,4.62 271.59,4.62 271.79,4.52 271.83,4.3 271.79,4.08 271.59,3.98 271.55,3.98 271.06,4.05 266.4,4.05 266.3,4.07 266.22,4.12 265.95,4.39 265.35,4.39 263.08,2.12 263,2.07 262.9,2.05 260.14,2.05 259.65,1.98 259.61,1.98
FG on TOP: 5.76,2.7 5.7,2.71 5.66,2.74 2.54,5.86 2.51,5.9 2.5,5.96 2.5,22.04 2.51,22.1 2.54,22.14 4.71,24.31 4.75,24.34 4.81,24.35 27.99,24.35 28.05,24.34 28.09,24.31 28.84,23.56 28.87,23.52 28.88,23.46 28.88,19.34 28.87,19.28 28.84,19.24 27.89,18.29 27.85,18.26 27.79,18.25 15.7,18.25 14.05,16.6 14.05,4.54 14.04,4.48 14.01,4.44 12.31,2.74 12.27,2.71 12.21,2.7
FG on TOP: 2.56,82.8 2.5,82.81 2.46,82.84 1.04,84.26 1.01,84.3 1,84.36 1,94.84 1.01,94.9 1.04,94.94 2.96,96.86 3,96.89 3.06,96.9 8.34,96.9 8.4,96.89 8.44,96.86 10.61,94.69 10.64,94.65 10.65,94.59 10.65,83.61 10.64,83.55 10.61,83.51 9.94,82.84 9.9,82.81 9.84,82.8
FG on BOTTOM: 287.35,1.1 287.24,1.14 287.2,1.25 287.2,3.94 287.21,4 287.24,4.04 287.6,4.4 287.6,8.79 287.64,8.89 287.75,8.94 289.69,8.94 291.26,10.51 291.3,10.54 291.36,10.55 297.39,10.55 297.45,10.54 297.49,10.51 298.16,9.84 298.19,9.8 298.2,9.74 298.2,2.96 298.19,2.9 298.16,2.86 296.44,1.14 296.4,1.11 296.34,1.1
FG on BOTTOM: 5.76,2.7 5.7,2.71 5.66,2.74 2.54,5.86 2.51,5.9 2.5,5.96 2.5,22.04 2.51,22.1 2.54,22.14 4.71,24.31 4.75,24.34 4.81,24.35 27.99,24.35 28.05,24.34 28.09,24.31 28.84,23.56 28.87,23.52 28.88,23.46 28.88,19.34 28.87,19.28 28.84,19.24 27.89,18.29 27.85,18.26 27.79,18.25 15.7,18.25 14.05,16.6 14.05,4.23 14.04,4.17 14.01,4.13 12.62,2.74 12.58,2.71 12.52,2.7
GDA on TOP: 123.25,7.78 123.25,8.02 122.91,8.26 122.87,8.46 123.07,8.52 123.09,8.51 123.46,8.24 123.8,8.24 124.05,8.49 124.05,9.54 123.94,9.92 123.93,9.99 123.96,10.05 124.04,10.11 124.15,10.1 124.18,10.08 124.2,10.05 124.21,10.07 124.24,10.09 124.27,10.11 124.41,10.09 124.47,9.96 124.46,9.92 124.35,9.54 124.35,8.43 124.34,8.37 123.76,7.78 123.09,7.29 123.07,7.28 122.87,7.34 122.91,7.54
GDA on CONDUCTIVE4: 123.65,9.85 113.66,9.85 113.6,9.86 113.55,9.89 111.54,11.9 111.51,11.95 111.5,12.01 111.5,15.03 111.51,15.09 111.54,15.14 112.04,15.63 112.04,92.26 108.72,95.57 108.69,95.62 108.68,95.68 108.68,100.14 108.69,100.2 109.34,100.86 110.3,101.62 110.34,101.64 110.37,101.65 110.39,101.65 110.52,101.59 110.54,101.46 110.52,101.43 110.5,101.4 110.49,101.39 110.04,101.03 110.04,100.45 110.49,100.09 110.5,100.08 110.52,100.05 110.54,100.02 110.52,99.89 110.39,99.83 110.37,99.83 110.34,99.84 110.3,99.86 109.6,100.41 109.31,100.41 108.98,100.08 108.98,95.74 112.3,92.43 112.33,92.38 112.34,92.32 112.34,15.57 112.33,15.51 112.3,15.46 111.8,14.97 111.8,12.07 113.72,10.15 123.65,10.15 124.09,10.31 124.28,10.22 124.19,10.02 124.13,10 124.19,9.98 124.28,9.78 124.09,9.69
LGND on TOP (solid shape): 235.18,54.38 235.08,54.72 235.42,54.81 236.9,53.85 236.77,53.63 235.42,52.89 235.08,52.98 235.18,53.32 235.39,53.44 235.39,54.26
LGND on TOP (solid shape): 279.12,14.63 279.72,14.83 280.66,14.47 280.98,14 280.66,13.53 279.72,13.17 279.63,13.15 279.54,13.14 279.08,13.45 279.2,14
LGND on BOTTOM (solid shape): 250.47,20.82 251.05,21.06 252.38,20.68 252.74,20.2 252.38,19.72 251.05,19.34 250.47,19.58 250.59,20.2
LGND on TOP: 271.56,5 271.5,5.01 271.46,5.04 271.34,5.16 271.31,5.2 271.3,5.26 271.3,9.05 271.34,9.16 271.45,9.2 272.55,9.2 272.66,9.16 272.7,9.05 272.7,5.26 272.69,5.2 272.66,5.16 272.54,5.04 272.5,5.01 272.44,5
LGND on TOP: 253.5,5.14 253.04,5.6 253.5,6.06 258.1,6.06 258.56,5.6 258.1,5.14
LGND on TOP: 277.69,88.24 277.58,88.28 277.54,88.39 277.54,92.21 277.55,92.27 277.58,92.31 278.5,93.23 278.5,100.17 278.54,100.28 278.65,100.32 280.3,100.32 280.41,100.28 280.45,100.17 280.45,97.88 281.44,96.89 283.55,96.89 283.61,96.88 283.65,96.85 285.33,95.17 285.36,95.13 285.37,95.07 285.37,92.57 285.36,92.51 285.33,92.47 281.14,88.28 281.1,88.25 281.04,88.24
LGND on TOP: 262.61,20 262.42,20.04 262.25,20.15 260.31,22.09 260.23,22.2 260.16,22.45 260.16,33.02 260.17,33.08 260.2,33.12 260.94,33.86 260.98,33.89 261.04,33.9 274.52,33.9 274.65,33.88 274.88,33.75 275.55,33.08 275.66,32.91 275.7,32.72 275.7,23.31 275.66,23.12 275.55,22.95 272.64,20.04 272.6,20.01 272.54,20
LGND on TOP: 264.61,35 264.55,35.01 264.51,35.04 264.3,35.25 263.75,35.25 263.69,35.19 263.65,35.16 263.59,35.15 263.26,35.15 263.2,35.16 263.16,35.19 263.09,35.26 263.06,35.3 263.05,35.36 263.05,35.69 263.06,35.75 263.09,35.79 263.11,35.81 263.15,35.84 263.21,35.85 263.59,35.85 263.65,35.84 263.69,35.81 263.75,35.75 263.9,35.75 264.75,36.6 264.75,39.52 265,39.77 265.25,39.52 265.25,36.81 265.3,36.2 265.3,35.3 265.21,35.09 265,35
LGND on BOTTOM: 286.5,1.31 286.4,1.35 286.35,1.46 286.35,3.69 285.9,4.15 285.39,4.46 285.28,4.72 285.48,4.92 285.68,5.12 285.94,5.01 286.25,4.5 286.75,4 286.76,3.99 286.79,3.95 286.8,3.89 286.8,1.46 286.76,1.35 286.65,1.31
LGND on BOTTOM: 256.58,118.66 256.15,119.08 256.58,119.51 257.59,119.51 257.65,119.51 257.7,119.5 258.24,119.35 259.56,119.35 259.6,119.39 259.64,119.42 259.7,119.43 260.43,119.43 260.49,119.42 260.53,119.39 260.55,119.37 261.35,119.37 261.45,119.33 261.5,119.22 261.5,118.95 261.45,118.84 261.35,118.8 260.5,118.8 260.45,118.76 260.39,118.75 259.57,118.75 259.51,118.76 259.46,118.79 259.42,118.83 258.3,118.83 257.7,118.67 257.65,118.66 257.59,118.66
LGND on BOTTOM: 272.05,6.26 272.04,6.38 272.15,6.76 272.15,7.45 272.1,7.5 272.03,7.5 271.53,6.99 271.48,6.96 271.43,6.95 268.75,6.95 268.69,6.96 268.64,6.99 268.49,7.14 268.46,7.19 268.45,7.25 268.45,7.4 268.38,7.73 268.41,7.85 268.53,7.91 268.6,7.89 268.67,7.91 268.79,7.85 268.82,7.73 268.75,7.4 268.75,7.31 268.81,7.25 271.36,7.25 271.93,7.82 272.11,8.1 272.37,8.19 272.52,7.97 272.52,7.8 272.52,7.75 272.45,7.42 272.45,6.76 272.56,6.38 272.57,6.31 272.54,6.25 272.49,6.2 272.42,6.19 272.35,6.2 272.3,6.25 272.23,6.19 272.14,6.19
LGND on BOTTOM: 256.4,70.04 256.17,70.1 256,70.28 255.68,70.87 253.34,73.2 252.56,73.99 236.04,73.99 235.48,73.42 235.45,73.4 235.41,73.38 235.36,73.36 235.3,73.35 234.78,73.35 234.7,73.3 234.61,73.28 234.27,73.28 234.18,73.3 234.1,73.35 234.05,73.4 234,73.48 233.98,73.57 233.98,73.75 234,73.84 234.05,73.92 234.17,74.04 234.25,74.09 234.34,74.11 234.48,74.11 234.57,74.09 234.65,74.04 234.84,73.85 235.2,73.85 235.76,74.42 235.84,74.47 235.94,74.49 252.66,74.49 252.76,74.47 252.84,74.42 256.03,71.22 256.52,70.96 257.01,70.96 257.11,70.95 257.2,70.92 257.52,70.77 257.84,70.92 257.93,70.95 258.03,70.96 258.7,70.96 258.75,70.96 259.68,70.96 259.74,70.95 259.78,70.92 260.05,70.65 260.79,70.65 260.96,70.82 261,70.85 261.06,70.86 263.2,70.86 263.31,70.82 263.35,70.71 263.35,70.46 263.31,70.35 263.2,70.31 262.08,70.31 262.01,70.24 261.97,70.21 261.91,70.2 259.9,70.2 259.78,70.08 259.74,70.05 259.68,70.04 258.75,70.04 258.7,70.04 258.03,70.04 257.93,70.05 257.84,70.08 257.52,70.23 257.2,70.08 257.11,70.05 257.01,70.04
LGND on BOTTOM: 262.46,20 262.4,20.01 262.36,20.04 259.54,22.86 259.51,22.9 259.5,22.96 259.5,32.69 259.51,32.75 259.54,32.8 259.95,33.2 259.99,33.23 260.05,33.24 274.37,33.24 274.43,33.23 274.48,33.2 275.57,32.11 275.6,32.07 275.61,32.01 275.61,23.07 275.6,23.01 275.57,22.97 272.64,20.04 272.6,20.01 272.54,20
LGND on BOTTOM: 249,77.31 248.94,77.32 248.89,77.35 248.08,78.17 248.05,78.21 248.04,78.27 248.04,82.68 248.05,82.73 248.08,82.78 248.1,82.8 248.1,83.65 248.14,83.76 248.25,83.8 251.15,83.8 251.26,83.76 251.3,83.65 251.3,82.17 251.67,81.8 253.51,81.8 253.94,82.23 253.94,83.65 253.98,83.76 254.09,83.8 256.95,83.8 257.06,83.76 257.1,83.65 257.1,82.2 257.5,81.8 259.22,81.8 259.71,82.29 259.71,83.7 259.75,83.81 259.86,83.85 262.75,83.85 262.86,83.81 262.9,83.7 262.9,82.12 262.89,82.07 262.86,82.02 261.34,80.5 261.34,77.66 261.33,77.6 261.29,77.56 261.09,77.35 261.04,77.32 260.99,77.31
LGND on BOTTOM: 248.45,124.4 248.39,124.41 248.35,124.44 248.31,124.48 248.28,124.52 248.27,124.58 248.27,127.67 247.94,128 247.91,128.04 247.9,128.1 247.9,130.9 247.94,131.01 248.05,131.05 250.95,131.05 251.06,131.01 251.1,130.9 251.1,129.37 251.47,129 253.29,129 253.69,129.4 253.69,130.9 253.73,131 253.84,131.05 256.79,131.05 256.9,131 256.94,130.9 256.94,129.38 257.32,129 259.1,129 259.5,129.4 259.5,130.89 259.54,131 259.65,131.04 262.55,131.04 262.66,131 262.7,130.89 262.7,129.66 262.69,129.6 262.66,129.56 261.2,128.1 261.2,124.96 261.19,124.9 261.16,124.86 260.74,124.44 260.7,124.41 260.64,124.4
LGND on BOTTOM: outline of 129 points within 266.3,120.08 295.26,133.85
LGND on BOTTOM: 244.48,3.57 244.37,3.61 244.33,3.71 244.32,3.73 244.32,3.84 244.33,3.89 244.4,4.2 244.33,4.51 244.32,4.56 244.32,4.67 244.4,4.84 244.56,4.9 244.62,4.9 244.68,4.89 244.72,4.86 245.08,4.5 247.29,4.5 247.67,4.61 247.74,4.62 247.8,4.59 247.85,4.54 247.86,4.47 247.85,4.4 247.8,4.35 247.85,4.3 247.86,4.23 247.8,4.11 247.67,4.09 247.29,4.2 245.08,4.2 244.82,3.94 244.82,3.72 244.78,3.61 244.68,3.57
LGND on BOTTOM: 239.75,127.88 239.64,127.92 239.6,128.03 239.6,129.22 239.61,129.28 239.64,129.32 240.36,130.04 240.4,130.07 240.46,130.08 241.73,130.08 241.84,130.04 241.88,129.93 241.88,129.67 241.84,129.56 241.73,129.52 241.65,129.52 240.44,128.31 240.44,128.03 240.4,127.92 240.29,127.88
LGND on BOTTOM: 240.52,78.83 240.41,78.87 240.37,78.98 240.37,80.52 240.38,80.58 240.41,80.62 241.94,82.15 241.98,82.18 242.04,82.19 242.33,82.19 242.44,82.15 242.48,82.04 242.48,80.47 242.47,80.41 242.44,80.37 240.94,78.87 240.9,78.84 240.84,78.83
LGND on BOTTOM: 237.72,1.3 237.31,1.72 237.72,2.13 238.36,2.13 238.45,2.12 238.53,2.1 239.05,1.87 239.65,1.87 239.88,2.11 239.93,2.14 239.99,2.15 240.37,2.26 240.46,2.26 240.5,2.27 240.54,2.26 240.88,2.14 240.91,2.13 241.07,1.97 241.69,1.97 241.8,1.93 241.84,1.82 241.84,1.57 241.8,1.46 241.69,1.42 241.26,1.42 241.2,1.43 241.15,1.46 240.9,1.72 239.92,1.72 239.81,1.61 239.76,1.58 239.71,1.57 239.05,1.57 238.53,1.34 238.45,1.31 238.36,1.3
LGND on BOTTOM: 234.25,118.67 234.16,118.69 234.02,118.83 234,118.92 234,119.08 234.02,119.17 234.07,119.25 234.09,119.27 234.17,119.32 234.26,119.34 234.41,119.34 234.5,119.32 234.58,119.27 234.64,119.21 235.86,119.21 237.36,120.72 237.44,120.77 237.54,120.79 253.06,120.79 253.16,120.77 253.24,120.72 254.18,119.77 254.77,119.45 254.83,119.41 254.87,119.35 254.89,119.16 254.76,119.01 254.69,118.99 254.61,118.99 254.61,118.91 254.59,118.84 254.44,118.71 254.25,118.73 254.19,118.77 254.15,118.83 253.83,119.42 252.96,120.29 237.64,120.29 236.14,118.78 236.11,118.76 236.07,118.74 236.02,118.72 235.96,118.71 234.67,118.71 234.61,118.68 234.53,118.67
LGND on BOTTOM: 280.5,13.47 279.72,13.17 279.63,13.15 279.54,13.14 279.13,13.34 279.07,13.8 279.12,13.91 279.2,14 279.12,14.09 279.07,14.2 279.13,14.66 279.54,14.86 279.63,14.85 279.72,14.83 280.5,14.53 281.66,14.86 282.22,14.63 282.15,14.02 282.13,14 282.15,13.98 282.22,13.37 281.66,13.14
LGND on BOTTOM: 268.44,45.73 268.46,45.87 268.5,46.01 268.92,46.95 268.94,46.99 268.97,47.03 270.27,48.33 270.35,48.38 270.45,48.4 271.25,48.4 272.08,48.82 272.5,49.65 272.5,49.7 272.52,49.8 272.57,49.88 273.99,51.3 274.07,51.35 274.17,51.37 274.37,51.37 274.55,51.3 274.62,51.12 274.62,50.58 274.55,50.4 274.37,50.33 273.73,50.33 273.02,49.61 273.55,48.56 273.57,48.52 273.43,48.21 273.11,48.33 272.87,48.8 272.7,48.8 272.69,48.63 272.57,48.51 272.45,48.45 272.39,48.33 272.36,48.28 272.31,48.24 272.21,48.2 272.1,48.2 272.1,48.03 272.57,47.79 272.62,47.76 272.66,47.71 272.68,47.45 272.46,47.32 272.4,47.33 272.34,47.35 271.25,47.9 270.55,47.9 269.45,46.79 269.79,46.01 269.83,45.87 269.85,45.73 269.85,36.25 269.15,35.55 268.44,36.25
LGND on BOTTOM: 269.33,74.4 269.27,74.41 269.23,74.44 267.94,75.73 267.91,75.77 267.9,75.83 267.9,80.66 267.6,80.96 267.02,80.96 266.96,80.97 266.92,81 266.22,81.7 265.7,81.7 265.59,81.74 265.55,81.85 265.55,82.29 265.56,82.35 265.59,82.39 265.89,82.69 265.89,83.7 265.93,83.81 266.04,83.85 268.95,83.85 269.06,83.81 269.1,83.7 269.1,82.04 269.34,81.8 271.26,81.8 271.7,82.24 271.7,83.7 271.74,83.81 271.85,83.85 274.75,83.85 274.86,83.81 274.9,83.7 274.9,81.91 275.01,81.8 276.97,81.8 277.5,82.33 277.5,83.7 277.54,83.81 277.65,83.85 280.85,83.85 280.95,83.81 281,83.7 281,82.37 281,82.34 281,75.16 280.99,75.1 280.96,75.06 280.34,74.44 280.3,74.41 280.24,74.4 273.9,74.4 273.84,74.41 273.8,74.44 273.37,74.87 273.34,74.92 273.32,74.98 273.32,75.88 271.9,75.88 271.9,74.99 271.89,74.93 271.86,74.88 271.42,74.44 271.38,74.41 271.32,74.4
LGND on BOTTOM: 256.93,10.38 256.87,10.39 256.83,10.42 256.74,10.51 256.71,10.55 256.7,10.61 256.7,12.15 256.74,12.26 256.85,12.3 258.65,12.3 259.16,12.81 259.2,12.84 259.26,12.85 259.85,12.85 259.96,12.81 260,12.7 260,11.15 260.16,10.99 260.19,10.95 260.2,10.89 260.2,10.53 260.16,10.42 260.05,10.38
LGND on CONDUCTIVE2: outline of 224 points within 235.06,1.55 298.45,143.8 ; 46 cut-outs
